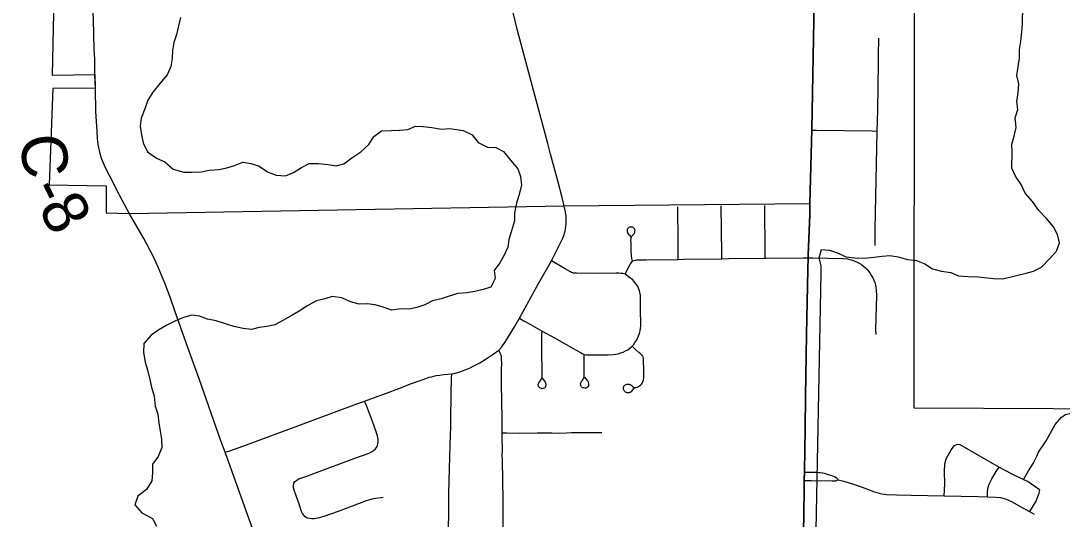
# Model space of a CAD drawing. Extents: x -21.7 to 34, y 0 to 22.
# Drawn here: x 26.689 to 27.989, y 17.848 to 18.47 of the extents above; entities that cross this region are included whole.
import ezdxf

# ---------------------------------------------------------------- set-up
doc = ezdxf.new("R2010")
doc.units = 0
for name, color, linetype in [('GM_X_City_Street', 7, 'Continuous'), ('GM_X_Corporation', 7, 'Continuous'), ('GM_X_County_Road', 7, 'Continuous'), ('GM_X_County_Road_Text', 7, 'Continuous'), ('GM_X_Interchange_Ramps', 7, 'Continuous'), ('GM_X_Minor_River', 7, 'Continuous')]:
    doc.layers.add(name, color=color, linetype=linetype)

msp = doc.modelspace()

# ---------------------------------------------------------------- linework, layer by layer
at = {"layer": 'GM_X_City_Street'}
for points in [[(27.7559, 18.1894), (27.7561, 18.2097), (27.7586, 18.3322), (27.7592, 18.3585), (27.7602, 18.4175), (27.7602, 18.4268), (27.7606, 18.4485)], [(27.6769, 18.3336), (27.6826, 18.3335), (27.7522, 18.3324), (27.7586, 18.3322)], [(27.5099, 18.1721), (27.5099, 18.1778), (27.51, 18.1936), (27.5094, 18.2377)], [(27.5645, 18.1729), (27.5644, 18.1786), (27.5636, 18.2388)], [(27.6187, 18.1736), (27.6187, 18.1795), (27.6187, 18.1921), (27.6181, 18.2268), (27.6182, 18.2392)], [(27.453, 18.1699), (27.4526, 18.1711), (27.4521, 18.1736), (27.4518, 18.1762), (27.4515, 18.1835), (27.4512, 18.1929), (27.4511, 18.196), (27.4512, 18.198), (27.4513, 18.1991), (27.4516, 18.2002), (27.4522, 18.2012), (27.4527, 18.2016), (27.4539, 18.2027), (27.4546, 18.2034), (27.4552, 18.2043), (27.4555, 18.2049), (27.4558, 18.2056), (27.456, 18.2064), (27.4561, 18.2073), (27.4562, 18.2084), (27.456, 18.2094), (27.4556, 18.2101), (27.4551, 18.2107), (27.4547, 18.2112), (27.4539, 18.2119), (27.453, 18.2123), (27.4523, 18.2125), (27.4516, 18.2126), (27.4504, 18.2125), (27.4492, 18.2122), (27.4486, 18.2119), (27.4473, 18.2108), (27.4468, 18.2101), (27.4465, 18.2093), (27.4463, 18.2084), (27.4463, 18.2074), (27.4464, 18.2067), (27.4466, 18.2058), (27.4469, 18.2051), (27.4473, 18.2044), (27.448, 18.2033), (27.4487, 18.2026), (27.4512, 18.1999)], [(27.4437, 18.1535), (27.4464, 18.159), (27.4488, 18.1635), (27.4496, 18.1649), (27.4503, 18.166), (27.4508, 18.1669), (27.4517, 18.1682), (27.453, 18.1699), (27.4549, 18.1708), (27.4564, 18.1713), (27.4579, 18.1716), (27.4607, 18.1717), (27.4701, 18.1716), (27.5099, 18.1721), (27.5168, 18.1722), (27.5645, 18.1729), (27.5729, 18.173), (27.6187, 18.1736), (27.6197, 18.1736), (27.6663, 18.1742), (27.6724, 18.174), (27.6762, 18.174), (27.6782, 18.1739), (27.7152, 18.1732), (27.7214, 18.1726), (27.7245, 18.172), (27.7276, 18.1711), (27.7305, 18.17), (27.7334, 18.1687), (27.7361, 18.1672), (27.7388, 18.1655), (27.7413, 18.1636), (27.7437, 18.1615), (27.7459, 18.1593), (27.7479, 18.1569), (27.7498, 18.1543), (27.7515, 18.1517), (27.753, 18.1489), (27.7543, 18.146), (27.7553, 18.1431), (27.7562, 18.14), (27.7568, 18.137), (27.7572, 18.1338), (27.7574, 18.1276), (27.7565, 18.0845), (27.7566, 18.0781)], [(27.3119, 18.0985), (27.3174, 18.0955), (27.3229, 18.0925), (27.3403, 18.0824), (27.3555, 18.0741), (27.3827, 18.0588), (27.388, 18.0557), (27.3903, 18.0546), (27.3926, 18.0535), (27.3946, 18.0531), (27.3977, 18.0527), (27.4041, 18.0528), (27.4227, 18.053), (27.429, 18.0532), (27.4322, 18.0537), (27.4353, 18.0543), (27.4384, 18.0552), (27.4414, 18.0563), (27.4442, 18.0577), (27.447, 18.0593), (27.4496, 18.0612), (27.4524, 18.0637), (27.4542, 18.0656), (27.4561, 18.0682), (27.4578, 18.0709), (27.4593, 18.0737), (27.4606, 18.0767), (27.4616, 18.0797), (27.4624, 18.0828), (27.4629, 18.0859), (27.4633, 18.0891), (27.4635, 18.0954), (27.4632, 18.1048), (27.4631, 18.1205), (27.4629, 18.1267), (27.4626, 18.1296), (27.4618, 18.133), (27.4607, 18.136), (27.4592, 18.139), (27.4573, 18.1417), (27.4551, 18.1444), (27.4528, 18.1468), (27.4506, 18.1487), (27.4477, 18.1508), (27.4455, 18.1524), (27.4437, 18.1535), (27.4409, 18.1544), (27.4389, 18.1546), (27.4358, 18.1548), (27.4326, 18.1549), (27.4045, 18.1546), (27.3829, 18.1548), (27.381, 18.1548), (27.3799, 18.1549), (27.3792, 18.155), (27.3784, 18.1552), (27.3768, 18.1559), (27.3748, 18.157), (27.3688, 18.1604), (27.3517, 18.1701)], [(27.3401, 18.0238), (27.343, 18.0199), (27.3439, 18.0187), (27.3443, 18.0181), (27.3446, 18.0175), (27.3449, 18.0163), (27.3449, 18.0154), (27.3448, 18.0144), (27.3446, 18.0136), (27.3442, 18.0129), (27.3439, 18.0123), (27.3434, 18.0117), (27.3427, 18.0112), (27.342, 18.0109), (27.3412, 18.0107), (27.3403, 18.0106), (27.3395, 18.0107), (27.3381, 18.0111), (27.3372, 18.0117), (27.3364, 18.0125), (27.3358, 18.0135), (27.3355, 18.0143), (27.3354, 18.015), (27.3353, 18.0157), (27.3354, 18.0165), (27.3356, 18.0173), (27.3359, 18.018), (27.339, 18.022), (27.3396, 18.0229), (27.3398, 18.0235), (27.34, 18.0244), (27.3401, 18.0252), (27.3401, 18.026), (27.3398, 18.0639), (27.3397, 18.0724), (27.3399, 18.0771), (27.3403, 18.0824)], [(26.9444, 17.9312), (26.9505, 17.9331), (26.971, 17.9404), (27.0353, 17.9643), (27.1054, 17.9904), (27.1185, 17.9951), (27.1491, 18.0064), (27.1667, 18.013), (27.176, 18.0166), (27.1893, 18.0214), (27.1949, 18.0235), (27.1992, 18.0249), (27.2019, 18.0256), (27.205, 18.0264), (27.2078, 18.027), (27.2123, 18.0277), (27.2172, 18.0283), (27.2274, 18.0292), (27.2295, 18.0296), (27.2337, 18.0305), (27.2375, 18.0317), (27.241, 18.0329), (27.2463, 18.0349), (27.2505, 18.0368), (27.2542, 18.0388), (27.2623, 18.0428), (27.2704, 18.0479), (27.2791, 18.0537), (27.286, 18.0589)], [(27.4546, 18.0117), (27.4532, 18.0094), (27.4522, 18.008), (27.4514, 18.0069), (27.4507, 18.0063), (27.4502, 18.006), (27.4494, 18.0057), (27.4487, 18.0055), (27.4474, 18.0055), (27.4463, 18.0056), (27.4456, 18.0057), (27.4449, 18.006), (27.4441, 18.0065), (27.4434, 18.007), (27.4429, 18.0075), (27.4424, 18.0084), (27.4421, 18.009), (27.4419, 18.0101), (27.4419, 18.012), (27.442, 18.0128), (27.4423, 18.0137), (27.4429, 18.0146), (27.4434, 18.015), (27.4442, 18.0156), (27.445, 18.0159), (27.4458, 18.0162), (27.4468, 18.0164), (27.4478, 18.0163), (27.4489, 18.0161), (27.45, 18.0158), (27.4513, 18.015), (27.4524, 18.0143), (27.4532, 18.0135), (27.4539, 18.0128), (27.4549, 18.0122), (27.4559, 18.0121), (27.4571, 18.0121), (27.4588, 18.0124), (27.4605, 18.0132), (27.4618, 18.014), (27.4634, 18.0153), (27.4642, 18.0163), (27.4652, 18.0177), (27.4659, 18.0192), (27.4664, 18.0203), (27.4668, 18.0214), (27.4669, 18.0224), (27.4671, 18.0241), (27.4672, 18.0256), (27.4671, 18.0294), (27.467, 18.0361), (27.4669, 18.0441), (27.4669, 18.0458), (27.4668, 18.047), (27.4666, 18.0484), (27.4664, 18.0498), (27.466, 18.0507), (27.4656, 18.0514), (27.465, 18.0523), (27.4644, 18.0529), (27.463, 18.0541), (27.4608, 18.056), (27.4567, 18.0595), (27.4524, 18.0637)], [(27.3929, 18.025), (27.3966, 18.0208), (27.3971, 18.0202), (27.3975, 18.0195), (27.3978, 18.0188), (27.398, 18.018), (27.3982, 18.0172), (27.3982, 18.0163), (27.3982, 18.0154), (27.398, 18.0142), (27.3973, 18.0129), (27.3969, 18.0125), (27.3963, 18.012), (27.3956, 18.0116), (27.395, 18.0114), (27.3943, 18.0113), (27.3935, 18.0113), (27.3919, 18.0115), (27.3912, 18.0117), (27.3905, 18.012), (27.3898, 18.0125), (27.3893, 18.013), (27.3888, 18.0137), (27.3885, 18.0144), (27.3884, 18.0151), (27.3883, 18.0159), (27.3883, 18.0173), (27.3885, 18.0181), (27.3888, 18.0188), (27.3894, 18.0198), (27.3899, 18.0205), (27.3907, 18.0214), (27.3915, 18.0224), (27.3919, 18.0232), (27.3922, 18.0239), (27.3924, 18.0246), (27.3926, 18.0252), (27.3928, 18.0269), (27.3926, 18.0391), (27.3927, 18.0483), (27.3926, 18.0535)], [(27.2234, 17.8353), (27.2238, 17.8565), (27.2238, 17.8798), (27.2246, 17.9108), (27.2257, 17.9533), (27.2257, 17.9562), (27.2261, 17.9589), (27.2263, 17.9708), (27.2267, 18.0047), (27.2271, 18.0233), (27.2274, 18.0292)], [(27.1419, 17.8748), (27.1389, 17.8743), (27.1327, 17.8737), (27.1295, 17.8732), (27.1265, 17.8724), (27.1204, 17.8706), (27.0854, 17.8572), (27.0678, 17.8509), (27.0618, 17.8493), (27.0557, 17.8483), (27.0527, 17.8482), (27.0497, 17.8484), (27.047, 17.8491), (27.0446, 17.8506), (27.0426, 17.8526), (27.041, 17.8549), (27.0399, 17.8575), (27.037, 17.8663), (27.0305, 17.8839), (27.0298, 17.8868), (27.0297, 17.8897), (27.0303, 17.8925), (27.0317, 17.8948), (27.0338, 17.8966), (27.0365, 17.898), (27.0453, 17.9011), (27.1066, 17.924), (27.1242, 17.9303), (27.1271, 17.9316), (27.1299, 17.9333), (27.1323, 17.9356), (27.1341, 17.9384), (27.1352, 17.9416), (27.1356, 17.9448), (27.1355, 17.9481), (27.1348, 17.9513), (27.1339, 17.9543), (27.1298, 17.9662), (27.1208, 17.9895), (27.1185, 17.9951)], [(27.9411, 17.8971), (27.9473, 17.9079), (27.953, 17.9174), (27.9576, 17.9263), (27.9598, 17.9314), (27.9695, 17.9456), (27.9806, 17.9661), (27.9887, 17.9752), (27.9933, 17.9786), (28.0007, 17.9802), (28.0207, 17.9807), (28.0889, 17.9806), (28.1363, 17.9803), (28.146, 17.9794), (28.1529, 17.9789)], [(27.2904, 17.9555), (27.296, 17.9554), (27.312, 17.9553), (27.334, 17.9556), (27.3525, 17.9556), (27.3614, 17.9551), (27.3705, 17.9554), (27.3767, 17.9558), (27.3904, 17.9559), (27.4021, 17.956), (27.4147, 17.956)], [(27.8422, 17.8767), (27.8428, 17.8915), (27.8423, 17.9072), (27.843, 17.9167), (27.8447, 17.923), (27.8509, 17.9344), (27.8549, 17.9397), (27.8588, 17.9415), (27.8617, 17.9408), (27.9108, 17.9126), (27.9168, 17.9094), (27.9273, 17.904), (27.9411, 17.8971), (27.9469, 17.8947), (27.9553, 17.8888), (27.961, 17.8846), (27.9604, 17.8798), (27.9565, 17.8703), (27.9486, 17.8572)], [(27.8961, 17.8756), (27.8963, 17.8822), (27.8968, 17.8876), (27.8981, 17.8915), (27.9014, 17.898), (27.9069, 17.9072), (27.9108, 17.9126)], [(27.668, 17.9066), (27.6766, 17.9063), (27.6824, 17.9063), (27.6854, 17.906), (27.6873, 17.9059), (27.69, 17.9055), (27.6924, 17.905), (27.6959, 17.904), (27.7014, 17.9022), (27.7059, 17.9004), (27.7075, 17.8993), (27.7083, 17.8987), (27.7092, 17.8975), (27.7096, 17.8967)], [(27.6677, 17.8962), (27.6762, 17.8961), (27.7022, 17.8956), (27.7054, 17.8955), (27.7067, 17.8956), (27.7076, 17.8958), (27.7096, 17.8967)], [(27.7096, 17.8967), (27.7169, 17.8952), (27.729, 17.8914), (27.7398, 17.8876), (27.7552, 17.8818), (27.7611, 17.8801), (27.7641, 17.8794), (27.7701, 17.8786), (27.7824, 17.878), (27.8009, 17.8775), (27.8422, 17.8767), (27.8844, 17.876), (27.8961, 17.8756), (27.9061, 17.8753), (27.9123, 17.8746), (27.9154, 17.874), (27.9184, 17.8731), (27.9214, 17.872), (27.9271, 17.8694), (27.9379, 17.8633), (27.9486, 17.8572), (27.9546, 17.8538)]]:
    msp.add_lwpolyline(points, dxfattribs=at)
at = {"layer": 'GM_X_Corporation'}
for points in [[(26.7301, 18.4797), (26.7284, 18.4023), (26.7817, 18.4029), (26.7824, 18.3857), (26.7295, 18.3855), (26.7247, 18.2653), (26.7958, 18.2639), (26.7958, 18.2301), (26.825, 18.2295), (27.3677, 18.2391), (27.6745, 18.2418), (27.6767, 18.3342), (27.6799, 18.4934)], [(27.8047, 18.4919), (27.804, 17.9866), (28.1528, 17.9852)]]:
    msp.add_lwpolyline(points, dxfattribs=at)
at = {"layer": 'GM_X_County_Road'}
for p, q in [((27.6769, 18.3336), (27.6801, 18.4929)), ((26.7826, 18.3852), (26.7819, 18.4023)), ((27.6747, 18.2423), (27.6769, 18.3336))]:
    msp.add_line(p, q, dxfattribs=at)
for points in [[(26.7819, 18.4023), (26.7817, 18.422), (26.7811, 18.4344), (26.78, 18.4717), (26.7798, 18.4794)], [(27.3679, 18.2386), (27.3675, 18.2406), (27.3653, 18.2495), (27.3596, 18.2701), (27.3507, 18.3034), (27.3474, 18.3166), (27.3328, 18.3708), (27.3094, 18.4578), (27.3036, 18.4819), (27.3033, 18.4837)], [(26.8253, 18.2289), (26.816, 18.2459), (26.8091, 18.2592), (26.8052, 18.2673), (26.7951, 18.2865), (26.7925, 18.2922), (26.7903, 18.2981), (26.7885, 18.3042), (26.7865, 18.3133), (26.7852, 18.3226), (26.7846, 18.332), (26.7833, 18.3567), (26.7826, 18.3852)], [(27.3119, 18.0985), (27.3357, 18.1421), (27.3517, 18.1701), (27.3606, 18.1876), (27.3637, 18.1935), (27.3661, 18.1987), (27.3673, 18.202), (27.3682, 18.2047), (27.3688, 18.2072), (27.3695, 18.2105), (27.3699, 18.2134), (27.3702, 18.2162), (27.3704, 18.2197), (27.3704, 18.2221), (27.3702, 18.2247), (27.37, 18.2266), (27.3694, 18.2305), (27.3689, 18.2331), (27.3679, 18.2386)], [(27.6724, 18.174), (27.6725, 18.1775), (27.6747, 18.2272), (27.6747, 18.2413), (27.6747, 18.2423)], [(26.9444, 17.9312), (26.9392, 17.9454), (26.9119, 18.0228), (26.8961, 18.0665), (26.8823, 18.1068), (26.8757, 18.1251), (26.8691, 18.1424), (26.8611, 18.1622), (26.8546, 18.1762), (26.8429, 18.1981), (26.8253, 18.2289)], [(27.6677, 17.8962), (27.668, 17.9066), (27.6686, 17.9598), (27.6692, 18.0002), (27.6704, 18.078), (27.6721, 18.1588), (27.6724, 18.174)], [(27.286, 18.0589), (27.2897, 18.0629), (27.2938, 18.0684), (27.2978, 18.075), (27.3057, 18.0877), (27.3119, 18.0985)], [(27.2904, 17.9555), (27.2903, 17.9728), (27.2896, 18.0166), (27.2896, 18.0352), (27.2897, 18.0422), (27.2896, 18.048), (27.2894, 18.0504), (27.289, 18.0526), (27.288, 18.055), (27.286, 18.0589)], [(27.2919, 17.8099), (27.2919, 17.8231), (27.2917, 17.8476), (27.2914, 17.8625), (27.2914, 17.8718), (27.2911, 17.8966), (27.2909, 17.9214), (27.2904, 17.9277), (27.2907, 17.933), (27.2908, 17.9359), (27.2904, 17.9481), (27.2904, 17.9555)], [(27.0032, 17.7693), (26.9999, 17.777), (26.9937, 17.7943), (26.9749, 17.8463), (26.9444, 17.9312)], [(27.665, 17.7336), (27.6666, 17.8292), (27.6675, 17.8821), (27.6677, 17.8962)]]:
    msp.add_lwpolyline(points, dxfattribs=at)
at = {"layer": 'GM_X_Interchange_Ramps'}
for points in [[(27.6664, 17.8297), (27.6673, 17.8826), (27.6675, 17.8968), (27.6677, 17.9072), (27.6684, 17.9604), (27.669, 18.0008), (27.6702, 18.0785), (27.6719, 18.1594), (27.6722, 18.1746), (27.6723, 18.1781), (27.6744, 18.2278), (27.6745, 18.2418), (27.6767, 18.3342), (27.6799, 18.4934)], [(27.6799, 18.4934), (27.6767, 18.3342), (27.6745, 18.2418), (27.6744, 18.2278), (27.6723, 18.1781), (27.6722, 18.1746), (27.6719, 18.1594), (27.6702, 18.0785), (27.669, 18.0008), (27.6684, 17.9604), (27.6677, 17.9072), (27.6675, 17.8968), (27.6673, 17.8826), (27.6664, 17.8297)]]:
    msp.add_lwpolyline(points, dxfattribs=at)
at = {"layer": 'GM_X_Minor_River'}
for points in [[(27.6885, 18.1547), (27.6887, 18.1641), (27.6862, 18.1741), (27.6891, 18.1846), (27.6989, 18.1837), (27.7091, 18.1804), (27.7192, 18.1753), (27.7306, 18.1739), (27.7427, 18.1737), (27.7541, 18.175), (27.7647, 18.1763), (27.7742, 18.1769), (27.7847, 18.1751), (27.7964, 18.1719), (27.8074, 18.1705), (27.8179, 18.1665), (27.8276, 18.1602), (27.8389, 18.1573), (27.8503, 18.1556), (27.86, 18.1516), (27.8714, 18.1506), (27.8846, 18.1503), (27.9036, 18.1484), (27.9145, 18.1478), (27.924, 18.1499), (27.9339, 18.1524), (27.9442, 18.1548), (27.9537, 18.1573), (27.9637, 18.1624), (27.9737, 18.1728), (27.9823, 18.1825), (27.9859, 18.1927), (27.9835, 18.203), (27.9787, 18.2126), (27.9698, 18.223), (27.9602, 18.2331), (27.9525, 18.2443), (27.9432, 18.2547), (27.9381, 18.2654), (27.9311, 18.2758), (27.9264, 18.2858), (27.9268, 18.3063), (27.9266, 18.3158), (27.9295, 18.326), (27.932, 18.3366), (27.9307, 18.3488), (27.9339, 18.3593), (27.9326, 18.3692), (27.9344, 18.3802), (27.9353, 18.3912), (27.9329, 18.4015), (27.9343, 18.4125), (27.936, 18.4238), (27.9362, 18.4341), (27.9376, 18.4443), (27.9389, 18.4564), (27.9399, 18.4663), (27.9403, 18.4883)], [(26.8889, 18.4739), (26.8863, 18.4637), (26.8838, 18.4527), (26.8805, 18.443), (26.8788, 18.4327), (26.8782, 18.4229), (26.8768, 18.413), (26.872, 18.4025), (26.863, 18.3917), (26.8544, 18.3809), (26.8481, 18.3708), (26.8441, 18.3599), (26.8396, 18.3486), (26.8386, 18.3384), (26.8399, 18.3277), (26.8423, 18.3178), (26.8477, 18.3063), (26.8589, 18.2984), (26.8691, 18.294), (26.8798, 18.2847), (26.893, 18.281), (26.9025, 18.2808), (26.9151, 18.2816), (26.9246, 18.2833), (26.9367, 18.2842), (26.9467, 18.2866), (26.9562, 18.2894), (26.9666, 18.2934), (26.9764, 18.292), (26.9862, 18.2888), (26.9981, 18.2809), (27.0083, 18.2773), (27.0197, 18.2766), (27.03, 18.2806), (27.04, 18.2868), (27.0496, 18.2919), (27.061, 18.2916), (27.0731, 18.2906), (27.0829, 18.2889), (27.0928, 18.2913), (27.1025, 18.2987), (27.1141, 18.3064), (27.1238, 18.3157), (27.1301, 18.3254), (27.1397, 18.3328), (27.1523, 18.3332), (27.1621, 18.3334), (27.1724, 18.3343), (27.182, 18.3383), (27.1915, 18.3381), (27.2024, 18.3367), (27.2145, 18.3345), (27.2248, 18.3354), (27.2418, 18.3331), (27.2527, 18.3276), (27.2604, 18.3179), (27.272, 18.3123), (27.2823, 18.3117), (27.292, 18.3066), (27.3009, 18.2958), (27.3097, 18.2853), (27.3133, 18.2754), (27.3146, 18.2647), (27.3112, 18.2519), (27.308, 18.2421), (27.3058, 18.2304), (27.3059, 18.2201), (27.3018, 18.2077), (27.2985, 18.1971), (27.2972, 18.1873), (27.2928, 18.1775), (27.2872, 18.1678), (27.2802, 18.1581), (27.2815, 18.1482), (27.2763, 18.1376), (27.2667, 18.1344), (27.256, 18.132), (27.2461, 18.1303), (27.2351, 18.1295), (27.2252, 18.1266), (27.2141, 18.1227), (27.2034, 18.1203), (27.1938, 18.1152), (27.1839, 18.112), (27.1743, 18.1099), (27.1641, 18.1102), (27.1523, 18.1085), (27.1418, 18.1126), (27.1316, 18.1154)], [(27.679, 17.6628), (27.6885, 18.1547)], [(27.1316, 18.1154), (27.1217, 18.1164), (27.1119, 18.1163), (27.1009, 18.1192), (27.09, 18.124), (27.0783, 18.1257), (27.0688, 18.1229), (27.0585, 18.1205), (27.0477, 18.1143), (27.0369, 18.1073), (27.0269, 18.1015), (27.0165, 18.0956), (27.0065, 18.0902), (26.9966, 18.0881), (26.9871, 18.0872), (26.9776, 18.0844), (26.967, 18.0857), (26.9553, 18.0883), (26.9436, 18.0919), (26.9334, 18.0952), (26.9225, 18.0973), (26.9127, 18.101), (26.9029, 18.1023), (26.8926, 18.0995), (26.8826, 18.0952), (26.8718, 18.0901), (26.8618, 18.0843), (26.8522, 18.0773), (26.8432, 18.0669), (26.8426, 18.0559), (26.8446, 18.0437), (26.8474, 18.0341), (26.8505, 18.0223), (26.8526, 18.0124), (26.8561, 18.0013), (26.8573, 17.9887), (26.8605, 17.9788), (26.8618, 17.9681), (26.8634, 17.9575), (26.8651, 17.9476), (26.8656, 17.9373), (26.8608, 17.926), (26.8537, 17.9163), (26.8539, 17.9061), (26.8532, 17.8954), (26.8462, 17.8846), (26.8357, 17.8765), (26.8317, 17.8656), (26.8405, 17.8555), (26.854, 17.8487), (26.8587, 17.8391)]]:
    msp.add_lwpolyline(points, dxfattribs=at)

# ---------------------------------------------------------------- texts
at = {"layer": 'GM_X_County_Road_Text'}
for s, rotation, p in [('C', 277.1807, (26.6876, 18.3251)), ('-', 295.6686, (26.6991, 18.2597)), ('8', 298.2196, (26.7104, 18.2362))]:
    msp.add_text(s, height=0.0568, rotation=rotation, dxfattribs=at).set_placement(p)

doc.saveas('drawing.dxf')
